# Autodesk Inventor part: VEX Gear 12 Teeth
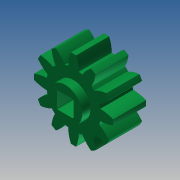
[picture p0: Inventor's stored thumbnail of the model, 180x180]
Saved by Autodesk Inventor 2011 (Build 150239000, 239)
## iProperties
Created: 2010-04
Part Number: VEX Gear 12 Teeth
Material: ABS Plastic
Document SubType Name: Modeling
Designer: Phil
Categories: <?xml version="1.0" encoding="UTF-16"?> <MemberInstance><Categories><FamilyTemplate><FamilyTemplateParameter ValueType="xs:double" Id="1" ObjectReferenceKey="da
Mass: 0.913644 g
Surface Area: 9.47061 cm^2
Volume: 0.861929 cm^3
Density: 1.06 g/cm^3
CustomPartVersion: 1
Author: Phil
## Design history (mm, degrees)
sketch "Sketch1"
  geometry: C1 r 7.62 at (0, 0)
  constraints: 1 centre point
  dimensions: "d0" = 15.24 diameter of C1 (= da_da)
extrude "Extrusion1" new body sketch "Sketch1" distance "d1" = 6.35 (= da_b); taper "d2" = 0 deg
sketch "Sketch2"
  geometry: C1 r 7.62 at (0, 0) reference; C2 r 6.35 at (0, 0)
  constraints: 1 centre point, 1 coincident
  dimensions: "d3" = 12.7 diameter of C2 (= da_dw)
feature "Pitch Diameter" sketch "Sketch2" dims "d4" = 76.2, "d5" = 0
workplane "Work Plane1"
workplane "Work Plane2"
workplane "Work Plane3"
feature "Spur Gear" dims "da_b" = 6.35, "da_d" = 12.7, "da_aw" = 50.8, "da_da" = 15.24, "da_df" = 10.4775, "da_dw" = 12.7, angle "da_beta" = 0 deg, "da_lefttooth" = 0, "da_righttooth" = 0
workplane "Work Plane4"
sketch "Sketch3"
  geometry: C1 r 3.251 at (0.498, -7.604); A1 r 7.62 centre (0.498, -7.604) between (-2.872, -0.77) and (-3.735, -1.268) reference; A2 r 7.62 centre (0.498, -7.604) between (-2.872, -0.77) and (-3.735, -1.268) reference; 1 further point
  constraints: 1 centre point, 1 coincident
  dimensions: "d20" = 6.5024 diameter of C1
extrude "Extrusion2" join sketch "Sketch3" stored distance "d21" = 9.525; taper "d22" = 0 deg
sketch "Sketch4"
  geometry: L1 (-1.359, -1.613)-(1.359, -1.613); L2 (1.613, -1.359)-(1.613, 1.359); L3 (1.359, 1.613)-(-1.359, 1.613); L4 (-1.613, 1.359)-(-1.613, -1.359); C1 r 3.251 at (0, 0) reference; A1 r 0.254 centre (-1.359, 1.359) between (-1.359, 1.613) and (-1.613, 1.359); A2 r 0.254 centre (1.359, 1.359) between (1.613, 1.359) and (1.359, 1.613); A3 r 0.254 centre (1.359, -1.359) between (1.359, -1.613) and (1.613, -1.359); A4 r 0.254 centre (-1.359, -1.359) between (-1.613, -1.359) and (-1.359, -1.613); 4 further points
  constraints: 8 end point, 8 point on circle, 8 tangent, 4 centre point, 4 point on line, 3 equal radius, 2 midpoint, 2 parallel, 2 perpendicular, 1 horizontal, 1 horizontal alignment, 1 vertical alignment
  dimensions: "d23" = 3.2258 distance of point (1.613, 1.613) point (-1.613, 1.613); "d24" = 0.254 radius of A1
extrude "Extrusion3" cut sketch "Sketch4" stored distance "d25" = 9.525; taper "d26" = 0 deg
body "Solid1"
body "Srf1"
node "Projected Loop1"
other parameters: "d6" = 0, "d7" = 15 deg (computed from da_z), "d9" = 0, "d14" = 0, "d15" = 50.8 (= da_aw), "d16" = 0, "d17" = 0, "d18" = 0, "d19" = 50.8 (= da_aw)
